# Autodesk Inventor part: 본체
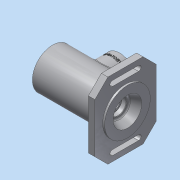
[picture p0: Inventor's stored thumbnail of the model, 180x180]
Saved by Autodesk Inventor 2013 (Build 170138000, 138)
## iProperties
Created: 2017-10
Part Number: 본체
Material: 알루미늄 6061
Document SubType Name: Modeling
Designer: dgall
Density: 2.71 g/cm^3
Mass: 738.119 g
Surface Area: 650.901 cm^2
Volume: 272.368 cm^3
Author: dgall
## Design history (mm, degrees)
revolve "회전1" stored, may be unused: angle "d31" = 90 deg
node "작업 평면1"
sketch "스케치2"
  geometry: L1 (-58, 47)-(58, 47); L2 (58, 47)-(58, -47); L3 (58, -47)-(-58, -47); L4 (-58, -47)-(-58, 47); L5 (-50, 20)-(-50, -20); L6 (-42, -20)-(-42, 20); L7 (42, 20)-(42, -20); L8 (50, -20)-(50, 20); C1 r 31 at (0, 0) reference; A1 r 4 centre (-46, -20) between (-50, -20) and (-42, -20); A2 r 4 centre (-46, 20) between (-42, 20) and (-50, 20); A3 r 4 centre (46, -20) between (42, -20) and (50, -20); A4 r 4 centre (46, 20) between (50, 20) and (42, 20); 3 further points
  constraints: 16 end point, 8 point on circle, 8 tangent, 4 centre point, 4 parallel, 3 horizontal alignment, 2 midpoint, 2 perpendicular, 1 equal radius, 1 horizontal, 1 vertical, 1 vertical alignment
  dimensions: "d33" = 94 distance between parallel lines of L3 L1; "d35" = 116 distance between parallel lines of L4 L2; "d36" = 40 distance of A3.centre A4.centre; "d37" = 20 vertical distance of A3.centre point (0, 0); "d38" = 92 distance of A3.centre A1.centre; "d39" = 46 horizontal distance of A1.centre point (0, 0); "d40" = 4 radius of A2
extrude "돌출1" join sketch "스케치2" distance "d41" = 10; taper "d42" = 0 deg
chamfer "모따기1" distance "d43" = 20; stored, may be unused: second distance "d44" = 2, angle "d45" = 45 deg
node "작업 평면3"
  node "작업 평면2"
sketch "스케치3"
  geometry: L1 (-51, -31)-(-51, 31) reference; C1 r 25 at (5, 0); 1 further point
  constraints: 1 centre point, 1 horizontal alignment
  dimensions: "d48" = 56 distance from line of L1 C1.centre; "d49" = 50 diameter of C1
extrude "돌출2" join sketch "스케치3" stored distance "d50" = 10; taper "d51" = 0 deg
hole "구멍1" diameter "d54" = 32; stored, may be unused: countersink angle "d58" = 90 deg, drill point angle "d60" = 118 deg; dims "d52" = 10, "d53" = 10, "d55" = 6, "d56" = 4, "d57" = 2, "d59" = 8
chamfer "모따기3" distance "d66" = 1; stored, may be unused: second distance "d67" = 2, angle "d68" = 45 deg
fillet "모깎기1" dims "d69" = 3
chamfer "모따기4" distance "d70" = 1; stored, may be unused: second distance "d71" = 2, angle "d72" = 45 deg
fillet "모깎기2" dims "d73" = 3
fillet "모깎기3" dims "d74" = 3
fillet "모깎기4" dims "d75" = 3
fillet "모깎기5" dims "d76" = 0.3
sketch "스케치4"
  geometry: C1 r 25 at (0, 0) reference; 3 further points
  constraints: 2 vertical alignment
  dimensions: "d77" = 41 distance of point (0, -20.5) point (0, 20.5); "d79" = 20.5 distance of C1.centre point (0, 20.5) (= 0.5 x d77)
hole "구멍2" sketch "스케치4" at (0, 20.5), (0, -20.5) diameter "d80" = 2.459; stored, may be unused: countersink angle "d84" = 90 deg, drill point angle "d86" = 118 deg; dims "d81" = 6, "d82" = 4, "d83" = 2, "d85" = 8
fillet "모깎기6" dims "d87" = 0.3
node "작업 평면5"
  node "작업 평면4"
sketch "스케치5"
  geometry: L1 (-26, -31)-(-26, 31) reference; L2 (5, 47)-(55, 47) reference; 2 further points
  constraints: 1 other
  dimensions: "d90" = 56 distance from line of point (30, 37) L1; "d91" = 10 distance from line of L2 point (30, 37)
feature "엠보싱1" sketch "스케치5" dims "d12" = 21, "d92" = 0.5, "d93" = 0
sketch "스케치6"
  geometry: C1 r 31 at (0, 0) reference; 1 further point
  constraints: 1 coincident
hole "구멍3" sketch "스케치6" at (0, 0) diameter "d95" = 40.376; stored, may be unused: countersink angle "d99" = 90 deg, drill point angle "d101" = 118 deg; dims "d96" = 6, "d97" = 4, "d98" = 2, "d100" = 9
chamfer "모따기5" distance "d102" = 1; stored, may be unused: second distance "d103" = 2, angle "d104" = 45 deg
node "솔리드1"
sketch "스케치1"
  geometry: L1 (-57.5, 0)-(57.5, 0); L2 (-57.5, 21)-(-57.5, 31); L3 (-57.5, 31)-(44.5, 31); L4 (44.5, 35)-(57.5, 35); L5 (57.5, 35)-(57.5, 22); L6 (44.5, 35)-(44.5, 31); L7 (-48.5, 21)-(-48.5, 24); L8 (-48.5, 24)-(-45.5, 24); L9 (-45.5, 24)-(-45.5, 20); L10 (-45.5, 20)-(-36.5, 20); L11 (-36.5, 20)-(-36.5, 17.5); L12 (-36.5, 17.5)-(-33.25, 17.5); L13 (-33.25, 17.5)-(-33.25, 18.5); L14 (-33.25, 18.5)-(-31.5, 18.5); L15 (-31.5, 18.5)-(-31.5, 17.5); L16 (-31.5, 17.5)-(-20.5, 17.5); L17 (-20.5, 17.5)-(-20.5, 26); L18 (-20.5, 26)-(17.5, 26); L19 (17.5, 26)-(17.5, 17.5); L20 (17.5, 17.5)-(28.5, 17.5); L21 (28.5, 17.5)-(28.5, 16.5); L22 (28.5, 16.5)-(33.5, 16.5); L23 (33.5, 16.5)-(33.5, 10); L24 (33.5, 10)-(36.2, 10); L25 (36.2, 10)-(36.2, 12.5); L26 (36.2, 12.5)-(42.8, 12.5); L27 (57.5, 22)-(43.5, 16); L28 (43.5, 16)-(43.5, 12.904); L29 (42.8, 12.5)-(43.5, 12.904); L30 (-57.5, 21)-(-57.5, 0); L31 (-48.5, 21)-(-48.5, 0); 2 further points
  constraints: 62 end point, 14 parallel, 7 perpendicular, 2 horizontal alignment, 2 vertical alignment, 1 coincident, 1 horizontal, 1 midpoint, 1 point on line
  dimensions: "d2" = 70 diameter of L4 L1; "d3" = 62 diameter of L3 L1; "d4" = 13 distance of L4.start L4.end; "d5" = 115 distance of L1.start L1.end; "d6" = 12 distance between parallel lines of L2 L9; "d7" = 3 distance of L7.end L8.end; "d9" = 48 diameter of L8 L1; "d10" = 40 diameter of L10 L1; "d11" = 35 diameter of L12 L1; "d12" = 21 distance between parallel lines of L2 L11; "d13" = 38 distance between parallel lines of L19 L17; "d14" = 26 distance between parallel lines of L2 L15; "d15" = 1.75 distance of L13.end L14.end; "d16" = 37 diameter of L14 L1; "d17" = 11 distance of L15.end L16.end; "d18" = 52 diameter of L18 L1; "d19" = 11 distance of L19.end L20.end; "d20" = 5 distance of L21.end L22.end; "d21" = 33 diameter of L22 L1; "d22" = 20 diameter of L24 L1; "d23" = 25 diameter of L26 L1; "d24" = 2.7 distance of L23.end L24.end; "d26" = 32 diameter of L27.end L1; "d27" = 30 deg angle of L26 L29; "d28" = 7.3 distance between parallel lines of L25 L28; "d29" = 0.7 horizontal distance of L28.end L26.end; "d30" = 44 diameter of L5.end L1; "d94" = 37 distance from line of L2.start L17
node "작업축1"
node "작업축2"
other parameters: "d32" = -13, "d46" = 0, "d47" = 47, "d88" = 0, "d89" = 45.75
